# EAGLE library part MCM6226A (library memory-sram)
MEMORY
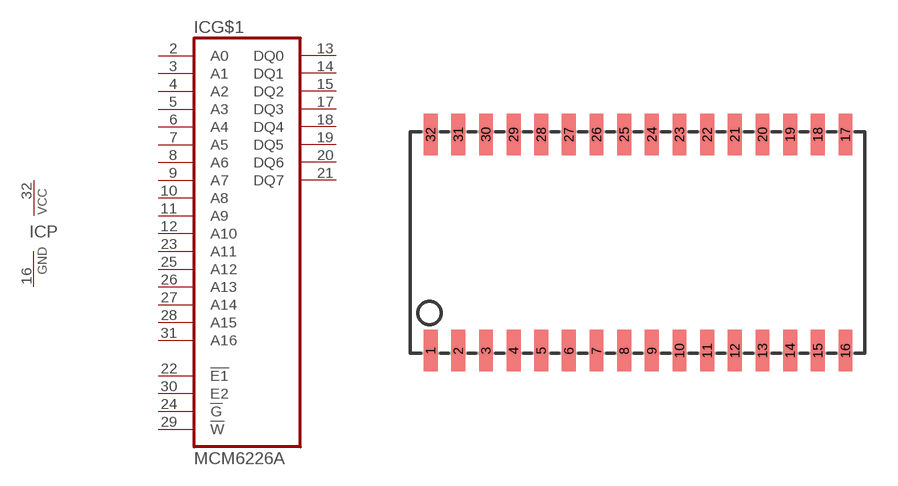
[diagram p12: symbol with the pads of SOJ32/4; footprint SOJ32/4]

Designator prefix IC; gates G$1=CM6226A P=PWRN

## MCM6226A  [SOJ32/4]
2  G$1:A0  in
3  G$1:A1  in
4  G$1:A2  in
5  G$1:A3  in
6  G$1:A4  in
7  G$1:A5  in
8  G$1:A6  in
9  G$1:A7  in
10  G$1:A8  in
11  G$1:A9  in
12  G$1:A10  in
13  G$1:DQ0
14  G$1:DQ1
15  G$1:DQ2
16  P:GND  pwr
17  G$1:DQ3
18  G$1:DQ4
19  G$1:DQ5
20  G$1:DQ6
21  G$1:DQ7
22  G$1:!E1  in
23  G$1:A11  in
24  G$1:!G  in
25  G$1:A12  in
26  G$1:A13  in
27  G$1:A14  in
28  G$1:A15  in
29  G$1:!W  in
30  G$1:E2  in
31  G$1:A16  in
32  P:VCC  pwr

## Footprint SOJ32/4 (pad centres in mm)
Small Outline J-Bend
smd 0.635 x 1.905: 1 -9.525,-4.966; 2 -8.255,-4.966; 3 -6.985,-4.966; 4 -5.715,-4.966; 5 -4.445,-4.966; 6 -3.175,-4.966; 7 -1.905,-4.966; 8 -0.635,-4.966; 9 0.635,-4.966; 10 1.905,-4.966; 11 3.175,-4.966; 12 4.445,-4.966; 13 5.715,-4.966; 14 6.985,-4.966; 15 8.255,-4.966; 16 9.525,-4.966; 17 9.525,4.966; 18 8.255,4.966; 19 6.985,4.966; 20 5.715,4.966; 21 4.445,4.966; 22 3.175,4.966; 23 1.905,4.966; 24 0.635,4.966; 25 -0.635,4.966; 26 -1.905,4.966; 27 -3.175,4.966; 28 -4.445,4.966; 29 -5.715,4.966; 30 -6.985,4.966; 31 -8.255,4.966; 32 -9.525,4.966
